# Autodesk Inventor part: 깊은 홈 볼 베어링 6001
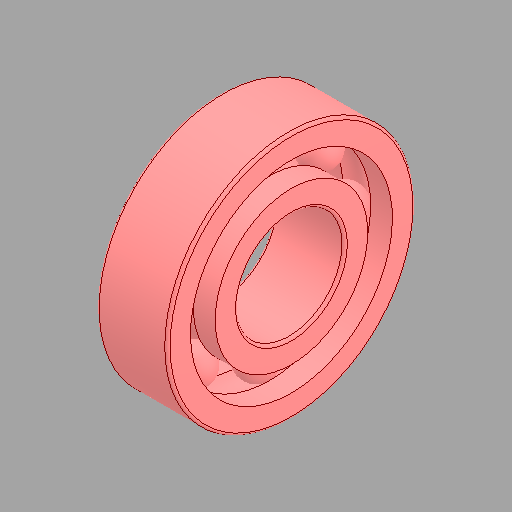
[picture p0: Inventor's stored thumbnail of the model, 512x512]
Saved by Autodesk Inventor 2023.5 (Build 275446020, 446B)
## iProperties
Created: 2026-03
Part Number: 깊은 홈 볼 베어링 6001
Material: 강철, 연강
Description: 깊은 그루브 볼 베어링
Document SubType Name: Modeling
Designer: mirae
Density: 7.85 g/cm^3
Appearance: 기본값
Author: jhkim
Sending System: Autodesk Inventor 2026
Preprocessor: ST-DEVELOPER v20.1
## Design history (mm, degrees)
node "깊은 홈 볼 베어링 60011"
node "솔리드1"
node "솔리드2"
node "솔리드3"
node "솔리드4"
node "솔리드5"
node "솔리드6"
node "솔리드7"
node "솔리드8"
node "솔리드9"
node "솔리드10"
body "Solid1"
node "Solid1:1"
node "Solid1:2"
node "Solid1:3"
node "Solid1:4"
node "Solid1:5"
node "Solid1:6"
node "Solid1:7"
node "Solid1:8"
node "Solid1:9"
